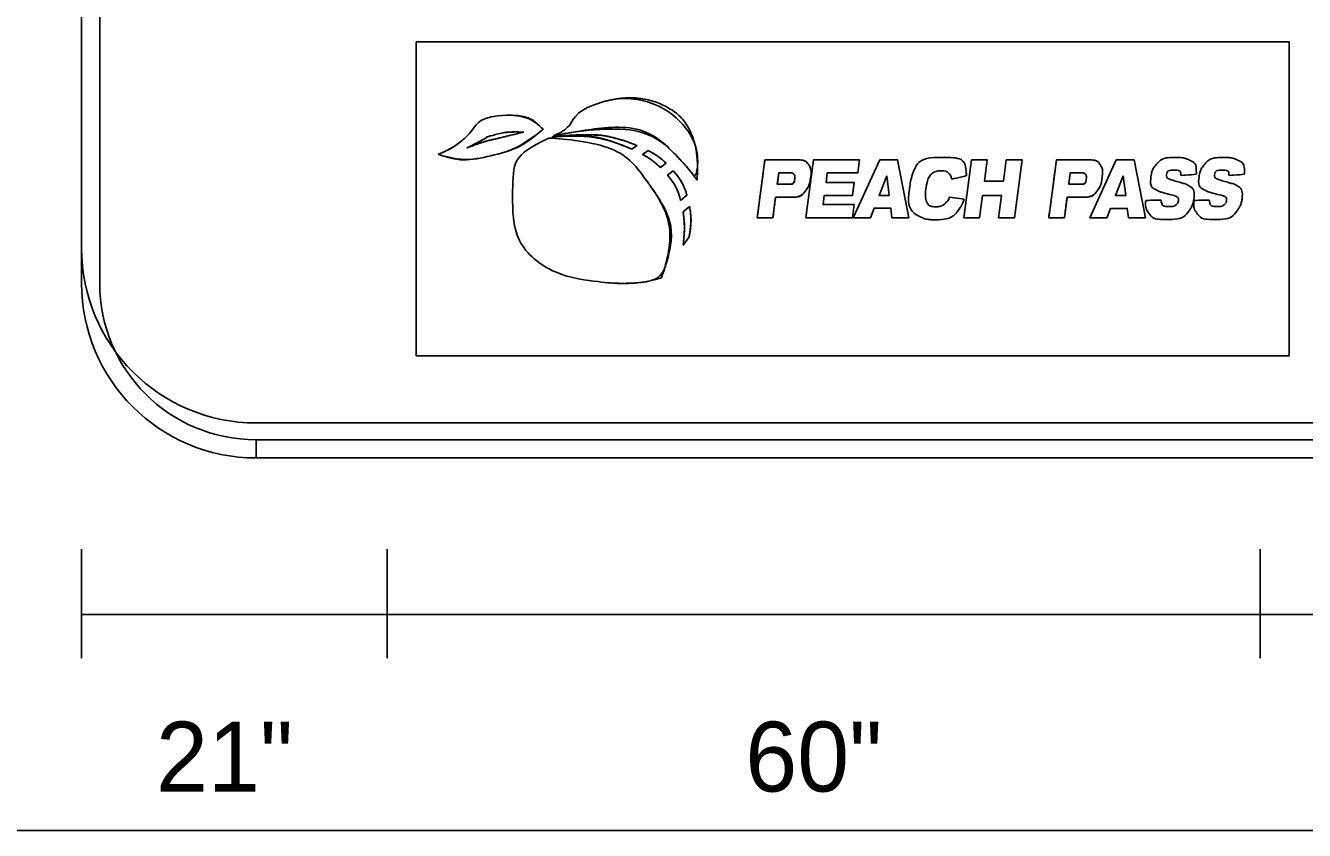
# Model space of a CAD drawing. Extents: x 10268259 to 10268554, y 2141099 to 2141249.
# Drawn here: x 10268353.87 to 10268367.06, y 2141173.53 to 2141181.82 of the extents above; entities that cross this region are included whole.
import ezdxf

# ---------------------------------------------------------------- set-up
doc = ezdxf.new("R2010")
doc.units = 0
for name, color, linetype in [('60', 7, 'Continuous'), ('Default', 7, 'Continuous'), ('GSColorFill', 7, 'Continuous'), ('GSDims', 7, 'Continuous'), ('GSSign', 7, 'Continuous'), ('Level 54', 7, 'Continuous')]:
    doc.layers.add(name, color=color, linetype=linetype)

# ---------------------------------------------------------------- blocks, each defined once
blk = doc.blocks.new('block 26')
at = {"layer": 'Default'}
for p, q in [((103520, 119763), (103447, 119726)), ((108216, 119013), (108535, 119227)), ((109207, 118923), (108863, 118693)), ((109932, 117915), (110273, 118175)), ((110708, 117718), (110360, 117454)), ((111148, 115944), (111527, 116249)), ((111687, 115575), (111294, 115257)), ((111296, 113252), (111655, 113756))]:
    blk.add_line(p, q, dxfattribs=at)
for points, degree in [([(106554, 121853), (104973, 121420), (104564, 120304), (103853, 119966), (103745, 119914), (103639, 119863), (103537, 119814)], 3), ([(106554, 121853), (104973, 121420), (104564, 120304), (103853, 119966), (103745, 119914), (103639, 119863), (103537, 119814), (105021, 120104), (108993, 120617), (111120, 118371), (111504, 117964), (111838, 117553), (112132, 117146), (112357, 120244), (108846, 122480), (106554, 121853)], 3), ([(112132, 117146), (112357, 120244), (108846, 122480), (106554, 121853)], 2), ([(100714, 121038), (99208, 121013), (98659, 120041), (98143, 119598), (97541, 119082), (96638, 118695), (96638, 118695), (96638, 118695), (98100, 118222), (99777, 118609), (101454, 118996), (102917, 120200), (102917, 120200), (102917, 120200), (101968, 121058), (100714, 121038)], 3), ([(100714, 121038), (99208, 121013), (98659, 120041), (98143, 119598), (97541, 119082), (96638, 118695), (96638, 118695)], 3), ([(102917, 120200), (102917, 120200), (101968, 121058), (100714, 121038)], 2), ([(103537, 119814), (105021, 120104), (108993, 120617), (111120, 118371), (111504, 117964), (111838, 117553), (112132, 117146)], 3), ([(96638, 118695), (96638, 118695), (98100, 118222), (99777, 118609), (101454, 118996), (102917, 120200), (102917, 120200)], 3), ([(99777, 119555), (99390, 119469), (98358, 119082), (98358, 119082)], 2), ([(99777, 119555), (99390, 119469), (98358, 119082), (98358, 119082), (99606, 119706), (99431, 119710), (100046, 119872), (100773, 120063), (101755, 120028), (101755, 120028), (100001, 119601), (100076, 119621), (99777, 119555)], 3), ([(98358, 119082), (99606, 119706), (99431, 119710), (100046, 119872), (100773, 120063), (101755, 120028), (101755, 120028)], 3), ([(101755, 120028), (100001, 119601), (100076, 119621), (99777, 119555)], 2), ([(103255, 119674), (101810, 118946), (101088, 118317), (101088, 116389), (101088, 113371), (103558, 111385), (106557, 111039), (107371, 110945), (109062, 111008), (109998, 111313), (110369, 112324), (110876, 114656), (109036, 117219), (107552, 119286), (104259, 119620), (103255, 119674)], 3), ([(103255, 119674), (101810, 118946), (101088, 118317), (101088, 116389), (101088, 113371), (103558, 111385), (106557, 111039), (107371, 110945), (109062, 111008), (109998, 111313)], 3), ([(109998, 111313), (110369, 112324), (110876, 114656), (109036, 117219), (107552, 119286), (104259, 119620), (103255, 119674)], 3), ([(108216, 119013), (108216, 119013), (108535, 119227), (108535, 119227), (106941, 119844), (105037, 119894), (103520, 119763), (103520, 119763), (103447, 119726), (103447, 119726), (104896, 119852), (106699, 119671), (108216, 119013)], 3), ([(103447, 119726), (104896, 119852), (106699, 119671), (108216, 119013)], 2), ([(108535, 119227), (106941, 119844), (105037, 119894), (103520, 119763)], 2), ([(110273, 118175), (109953, 118471), (109593, 118718), (109207, 118923), (109207, 118923), (108863, 118693), (108863, 118693), (109252, 118473), (109614, 118215), (109932, 117915), (109932, 117915), (110273, 118175), (110273, 118175)], 3), ([(108863, 118693), (109252, 118473), (109614, 118215), (109932, 117915)], 2), ([(110273, 118175), (109953, 118471), (109593, 118718), (109207, 118923)], 2), ([(110708, 117718), (110708, 117718), (110360, 117454), (110360, 117454), (110717, 117016), (110983, 116522), (111148, 115944), (111148, 115944), (111527, 116249), (111527, 116249), (111359, 116773), (111089, 117264), (110708, 117718)], 3), ([(110360, 117454), (110717, 117016), (110983, 116522), (111148, 115944)], 2), ([(111527, 116249), (111359, 116773), (111089, 117264), (110708, 117718)], 2), ([(111294, 115257), (111377, 114673), (111380, 114012), (111296, 113252), (111296, 113252), (111655, 113756), (111655, 113756), (111762, 114396), (111776, 115003), (111687, 115575), (111687, 115575), (111294, 115257), (111294, 115257)], 3), ([(111294, 115257), (111377, 114673), (111380, 114012), (111296, 113252)], 2), ([(111655, 113756), (111762, 114396), (111776, 115003), (111687, 115575)], 2)]:
    blk.add_open_spline(points, degree=degree, dxfattribs=at)

msp = doc.modelspace()

# ---------------------------------------------------------------- linework, layer by layer
at = {"layer": '60'}
msp.add_line((10268341.73, 2141173.528), (10268393.98, 2141173.528), dxfattribs=at)
at = {"layer": 'Default'}
for p, q in [((10268361.915, 2141179.843), (10268361.994, 2141180.439)), ((10268361.994, 2141180.439), (10268362.469, 2141180.439)), ((10268362.406, 2141179.843), (10268362.679, 2141180.439)), ((10268362.469, 2141180.439), (10268362.451, 2141180.304)), ((10268362.679, 2141180.439), (10268362.863, 2141180.439)), ((10268362.863, 2141180.439), (10268362.98, 2141179.843)), ((10268363.545, 2141179.843), (10268363.624, 2141180.439)), ((10268363.624, 2141180.439), (10268363.786, 2141180.439)), ((10268363.786, 2141180.439), (10268363.758, 2141180.221)), ((10268363.954, 2141180.221), (10268363.983, 2141180.439)), ((10268363.983, 2141180.439), (10268364.147, 2141180.439)), ((10268364.147, 2141180.439), (10268364.068, 2141179.843)), ((10268364.844, 2141179.842), (10268365.117, 2141180.438)), ((10268365.117, 2141180.438), (10268365.301, 2141180.438)), ((10268365.301, 2141180.438), (10268365.417, 2141179.842)), ((10268362.138, 2141180.304), (10268362.125, 2141180.207)), ((10268362.451, 2141180.304), (10268362.138, 2141180.304)), ((10268362.75, 2141180.273), (10268362.671, 2141180.071)), ((10268362.776, 2141180.071), (10268362.75, 2141180.273)), ((10268365.188, 2141180.273), (10268365.109, 2141180.071)), ((10268365.214, 2141180.071), (10268365.188, 2141180.273)), ((10268362.125, 2141180.207), (10268362.415, 2141180.207)), ((10268362.415, 2141180.207), (10268362.397, 2141180.072)), ((10268363.758, 2141180.221), (10268363.954, 2141180.221)), ((10268362.106, 2141180.072), (10268362.094, 2141179.978)), ((10268362.397, 2141180.072), (10268362.106, 2141180.072)), ((10268362.671, 2141180.071), (10268362.776, 2141180.071)), ((10268363.738, 2141180.071), (10268363.708, 2141179.843)), ((10268363.935, 2141180.071), (10268363.738, 2141180.071)), ((10268363.904, 2141179.843), (10268363.935, 2141180.071)), ((10268365.109, 2141180.071), (10268365.214, 2141180.071)), ((10268362.094, 2141179.978), (10268362.414, 2141179.978)), ((10268362.414, 2141179.978), (10268362.397, 2141179.843)), ((10268362.62, 2141179.94), (10268362.583, 2141179.843)), ((10268362.793, 2141179.94), (10268362.62, 2141179.94)), ((10268362.804, 2141179.843), (10268362.793, 2141179.94)), ((10268365.058, 2141179.939), (10268365.021, 2141179.842)), ((10268365.23, 2141179.939), (10268365.058, 2141179.939)), ((10268365.242, 2141179.842), (10268365.23, 2141179.939)), ((10268362.397, 2141179.843), (10268361.915, 2141179.843)), ((10268362.583, 2141179.843), (10268362.406, 2141179.843)), ((10268362.98, 2141179.843), (10268362.804, 2141179.843)), ((10268363.708, 2141179.843), (10268363.545, 2141179.843)), ((10268364.068, 2141179.843), (10268363.904, 2141179.843)), ((10268365.021, 2141179.842), (10268364.844, 2141179.842)), ((10268365.417, 2141179.842), (10268365.242, 2141179.842))]:
    msp.add_line(p, q, dxfattribs=at)
for points in [[(10268361.726, 2141180.053), (10268361.604, 2141180.053), (10268361.577, 2141179.843), (10268361.416, 2141179.843), (10268361.494, 2141180.439), (10268361.803, 2141180.439)], [(10268362.469, 2141180.439), (10268362.451, 2141180.304), (10268362.138, 2141180.304), (10268362.125, 2141180.207), (10268362.415, 2141180.207), (10268362.397, 2141180.072), (10268362.106, 2141180.072), (10268362.094, 2141179.978), (10268362.414, 2141179.978), (10268362.397, 2141179.843), (10268361.915, 2141179.843), (10268361.994, 2141180.439), (10268362.469, 2141180.439)], [(10268362.679, 2141180.439), (10268362.863, 2141180.439), (10268362.98, 2141179.843), (10268362.804, 2141179.843), (10268362.793, 2141179.94), (10268362.62, 2141179.94), (10268362.583, 2141179.843), (10268362.406, 2141179.843), (10268362.679, 2141180.439)], [(10268363.624, 2141180.439), (10268363.786, 2141180.439), (10268363.758, 2141180.221), (10268363.954, 2141180.221), (10268363.983, 2141180.439), (10268364.147, 2141180.439), (10268364.068, 2141179.843), (10268363.904, 2141179.843), (10268363.935, 2141180.071), (10268363.738, 2141180.071), (10268363.708, 2141179.843), (10268363.545, 2141179.843), (10268363.624, 2141180.439)], [(10268364.732, 2141180.053), (10268364.61, 2141180.053), (10268364.582, 2141179.842), (10268364.421, 2141179.842), (10268364.5, 2141180.439), (10268364.808, 2141180.439)], [(10268365.117, 2141180.438), (10268365.301, 2141180.438), (10268365.417, 2141179.842), (10268365.242, 2141179.842), (10268365.23, 2141179.939), (10268365.058, 2141179.939), (10268365.021, 2141179.842), (10268364.844, 2141179.842), (10268365.117, 2141180.438)], [(10268361.755, 2141180.304), (10268361.637, 2141180.304), (10268361.622, 2141180.187), (10268361.727, 2141180.187)], [(10268362.75, 2141180.273), (10268362.671, 2141180.071), (10268362.776, 2141180.071), (10268362.75, 2141180.273)], [(10268364.761, 2141180.304), (10268364.643, 2141180.304), (10268364.628, 2141180.187), (10268364.732, 2141180.187)], [(10268365.188, 2141180.273), (10268365.109, 2141180.071), (10268365.214, 2141180.071), (10268365.188, 2141180.273)]]:
    msp.add_lwpolyline(points, dxfattribs=at)
for points in [[(10268361.494, 2141180.439), (10268361.494, 2141180.439), (10268361.803, 2141180.439), (10268361.803, 2141180.439), (10268361.86, 2141180.438), (10268361.912, 2141180.436), (10268361.942, 2141180.394), (10268361.956, 2141180.373), (10268361.976, 2141180.33), (10268361.965, 2141180.248), (10268361.959, 2141180.208), (10268361.946, 2141180.162), (10268361.918, 2141180.125), (10268361.868, 2141180.058), (10268361.8, 2141180.053), (10268361.726, 2141180.053), (10268361.726, 2141180.053), (10268361.604, 2141180.053), (10268361.604, 2141180.053), (10268361.604, 2141180.053), (10268361.577, 2141179.843), (10268361.577, 2141179.843), (10268361.577, 2141179.843), (10268361.416, 2141179.843), (10268361.416, 2141179.843), (10268361.416, 2141179.843), (10268361.494, 2141180.439), (10268361.494, 2141180.439)], [(10268361.803, 2141180.439), (10268361.86, 2141180.438), (10268361.912, 2141180.436), (10268361.942, 2141180.394), (10268361.956, 2141180.373), (10268361.976, 2141180.33), (10268361.965, 2141180.248), (10268361.959, 2141180.208), (10268361.946, 2141180.162), (10268361.918, 2141180.125), (10268361.868, 2141180.058), (10268361.8, 2141180.053), (10268361.726, 2141180.053)], [(10268363.154, 2141180.14), (10268363.142, 2141180.05), (10268363.17, 2141179.956), (10268363.262, 2141179.956), (10268363.297, 2141179.956), (10268363.332, 2141179.971), (10268363.359, 2141179.996), (10268363.383, 2141180.019), (10268363.392, 2141180.038), (10268363.399, 2141180.056), (10268363.399, 2141180.056), (10268363.55, 2141180.035), (10268363.55, 2141180.035), (10268363.542, 2141180.013), (10268363.534, 2141179.991), (10268363.515, 2141179.961), (10268363.448, 2141179.853), (10268363.34, 2141179.822), (10268363.241, 2141179.822), (10268363.197, 2141179.822), (10268363.155, 2141179.827), (10268363.115, 2141179.844), (10268363.028, 2141179.882), (10268362.963, 2141179.976), (10268362.985, 2141180.14), (10268363, 2141180.255), (10268363.074, 2141180.464), (10268363.331, 2141180.464), (10268363.55, 2141180.464), (10268363.567, 2141180.332), (10268363.574, 2141180.275), (10268363.574, 2141180.275), (10268363.42, 2141180.24), (10268363.42, 2141180.24), (10268363.416, 2141180.257), (10268363.411, 2141180.28), (10268363.39, 2141180.3), (10268363.368, 2141180.32), (10268363.339, 2141180.327), (10268363.316, 2141180.327), (10268363.244, 2141180.327), (10268363.17, 2141180.267), (10268363.154, 2141180.14)], [(10268363.154, 2141180.14), (10268363.142, 2141180.05), (10268363.17, 2141179.956), (10268363.262, 2141179.956), (10268363.297, 2141179.956), (10268363.332, 2141179.971), (10268363.359, 2141179.996), (10268363.383, 2141180.019), (10268363.392, 2141180.038), (10268363.399, 2141180.056), (10268363.399, 2141180.056), (10268363.55, 2141180.035), (10268363.55, 2141180.035), (10268363.542, 2141180.013), (10268363.534, 2141179.991), (10268363.515, 2141179.961), (10268363.448, 2141179.853), (10268363.34, 2141179.822), (10268363.241, 2141179.822), (10268363.197, 2141179.822), (10268363.155, 2141179.827), (10268363.115, 2141179.844), (10268363.028, 2141179.882), (10268362.963, 2141179.976), (10268362.985, 2141180.14), (10268363, 2141180.255), (10268363.074, 2141180.464), (10268363.331, 2141180.464), (10268363.55, 2141180.464), (10268363.567, 2141180.332), (10268363.574, 2141180.275), (10268363.574, 2141180.275), (10268363.42, 2141180.24), (10268363.42, 2141180.24), (10268363.416, 2141180.257), (10268363.411, 2141180.28), (10268363.39, 2141180.3), (10268363.368, 2141180.32), (10268363.339, 2141180.327), (10268363.316, 2141180.327), (10268363.244, 2141180.327), (10268363.17, 2141180.267), (10268363.154, 2141180.14)], [(10268364.5, 2141180.439), (10268364.5, 2141180.439), (10268364.808, 2141180.439), (10268364.808, 2141180.439), (10268364.866, 2141180.438), (10268364.918, 2141180.436), (10268364.948, 2141180.394), (10268364.962, 2141180.373), (10268364.981, 2141180.33), (10268364.97, 2141180.248), (10268364.965, 2141180.208), (10268364.952, 2141180.162), (10268364.924, 2141180.125), (10268364.874, 2141180.058), (10268364.805, 2141180.053), (10268364.732, 2141180.053), (10268364.732, 2141180.053), (10268364.61, 2141180.053), (10268364.61, 2141180.053), (10268364.61, 2141180.053), (10268364.582, 2141179.842), (10268364.582, 2141179.842), (10268364.582, 2141179.842), (10268364.421, 2141179.842), (10268364.421, 2141179.842), (10268364.421, 2141179.842), (10268364.5, 2141180.439), (10268364.5, 2141180.439)], [(10268364.808, 2141180.439), (10268364.866, 2141180.438), (10268364.918, 2141180.436), (10268364.948, 2141180.394), (10268364.962, 2141180.373), (10268364.981, 2141180.33), (10268364.97, 2141180.248), (10268364.965, 2141180.208), (10268364.952, 2141180.162), (10268364.924, 2141180.125), (10268364.874, 2141180.058), (10268364.805, 2141180.053), (10268364.732, 2141180.053)], [(10268365.634, 2141180.285), (10268365.633, 2141180.276), (10268365.633, 2141180.269), (10268365.636, 2141180.264), (10268365.644, 2141180.245), (10268365.688, 2141180.232), (10268365.712, 2141180.225), (10268365.741, 2141180.215), (10268365.772, 2141180.208), (10268365.801, 2141180.199), (10268365.82, 2141180.194), (10268365.839, 2141180.188), (10268365.856, 2141180.178), (10268365.912, 2141180.148), (10268365.924, 2141180.089), (10268365.917, 2141180.035), (10268365.911, 2141179.995), (10268365.897, 2141179.959), (10268365.88, 2141179.933), (10268365.832, 2141179.858), (10268365.752, 2141179.825), (10268365.63, 2141179.825), (10268365.585, 2141179.825), (10268365.496, 2141179.83), (10268365.451, 2141179.892), (10268365.418, 2141179.938), (10268365.419, 2141179.993), (10268365.421, 2141180.02), (10268365.421, 2141180.02), (10268365.58, 2141180.026), (10268365.58, 2141180.026), (10268365.581, 2141179.987), (10268365.607, 2141179.957), (10268365.671, 2141179.957), (10268365.687, 2141179.957), (10268365.711, 2141179.96), (10268365.729, 2141179.972), (10268365.741, 2141179.98), (10268365.755, 2141179.997), (10268365.757, 2141180.017), (10268365.761, 2141180.045), (10268365.745, 2141180.057), (10268365.733, 2141180.063), (10268365.715, 2141180.071), (10268365.616, 2141180.095), (10268365.595, 2141180.102), (10268365.578, 2141180.107), (10268365.562, 2141180.112), (10268365.546, 2141180.12), (10268365.529, 2141180.129), (10268365.462, 2141180.162), (10268365.476, 2141180.271), (10268365.482, 2141180.316), (10268365.501, 2141180.357), (10268365.528, 2141180.388), (10268365.587, 2141180.457), (10268365.679, 2141180.464), (10268365.729, 2141180.464), (10268365.784, 2141180.464), (10268365.837, 2141180.454), (10268365.863, 2141180.441), (10268365.943, 2141180.406), (10268365.942, 2141180.322), (10268365.943, 2141180.29), (10268365.943, 2141180.29), (10268365.783, 2141180.278), (10268365.783, 2141180.278), (10268365.782, 2141180.297), (10268365.779, 2141180.333), (10268365.711, 2141180.333), (10268365.69, 2141180.333), (10268365.639, 2141180.329), (10268365.634, 2141180.285)], [(10268365.634, 2141180.285), (10268365.633, 2141180.276), (10268365.633, 2141180.269), (10268365.636, 2141180.264), (10268365.644, 2141180.245), (10268365.688, 2141180.232), (10268365.712, 2141180.225), (10268365.741, 2141180.215), (10268365.772, 2141180.208), (10268365.801, 2141180.199), (10268365.82, 2141180.194), (10268365.839, 2141180.188), (10268365.856, 2141180.178), (10268365.912, 2141180.148), (10268365.924, 2141180.089), (10268365.917, 2141180.035), (10268365.911, 2141179.995), (10268365.897, 2141179.959), (10268365.88, 2141179.933), (10268365.832, 2141179.858), (10268365.752, 2141179.825), (10268365.63, 2141179.825), (10268365.585, 2141179.825), (10268365.496, 2141179.83), (10268365.451, 2141179.892), (10268365.418, 2141179.938), (10268365.419, 2141179.993), (10268365.421, 2141180.02), (10268365.421, 2141180.02), (10268365.58, 2141180.026), (10268365.58, 2141180.026), (10268365.581, 2141179.987), (10268365.607, 2141179.957), (10268365.671, 2141179.957), (10268365.687, 2141179.957), (10268365.711, 2141179.96), (10268365.729, 2141179.972), (10268365.741, 2141179.98), (10268365.755, 2141179.997), (10268365.757, 2141180.017), (10268365.761, 2141180.045), (10268365.745, 2141180.057), (10268365.733, 2141180.063), (10268365.715, 2141180.071), (10268365.616, 2141180.095), (10268365.595, 2141180.102), (10268365.578, 2141180.107), (10268365.562, 2141180.112), (10268365.546, 2141180.12), (10268365.529, 2141180.129), (10268365.462, 2141180.162), (10268365.476, 2141180.271), (10268365.482, 2141180.316), (10268365.501, 2141180.357), (10268365.528, 2141180.388), (10268365.587, 2141180.457), (10268365.679, 2141180.464), (10268365.729, 2141180.464), (10268365.784, 2141180.464), (10268365.837, 2141180.454), (10268365.863, 2141180.441), (10268365.943, 2141180.406), (10268365.942, 2141180.322), (10268365.943, 2141180.29), (10268365.943, 2141180.29), (10268365.783, 2141180.278), (10268365.783, 2141180.278), (10268365.782, 2141180.297), (10268365.779, 2141180.333), (10268365.711, 2141180.333), (10268365.69, 2141180.333), (10268365.639, 2141180.329), (10268365.634, 2141180.285)], [(10268366.13, 2141180.285), (10268366.129, 2141180.276), (10268366.13, 2141180.269), (10268366.132, 2141180.264), (10268366.141, 2141180.245), (10268366.184, 2141180.232), (10268366.208, 2141180.225), (10268366.238, 2141180.215), (10268366.268, 2141180.208), (10268366.297, 2141180.199), (10268366.316, 2141180.194), (10268366.335, 2141180.188), (10268366.353, 2141180.178), (10268366.409, 2141180.148), (10268366.42, 2141180.089), (10268366.413, 2141180.035), (10268366.408, 2141179.995), (10268366.393, 2141179.959), (10268366.376, 2141179.933), (10268366.328, 2141179.858), (10268366.248, 2141179.825), (10268366.127, 2141179.825), (10268366.081, 2141179.825), (10268365.992, 2141179.83), (10268365.947, 2141179.892), (10268365.914, 2141179.938), (10268365.916, 2141179.993), (10268365.917, 2141180.02), (10268365.917, 2141180.02), (10268366.077, 2141180.026), (10268366.077, 2141180.026), (10268366.077, 2141179.987), (10268366.103, 2141179.957), (10268366.167, 2141179.957), (10268366.184, 2141179.957), (10268366.208, 2141179.96), (10268366.225, 2141179.972), (10268366.237, 2141179.98), (10268366.251, 2141179.997), (10268366.253, 2141180.017), (10268366.257, 2141180.045), (10268366.242, 2141180.057), (10268366.23, 2141180.063), (10268366.211, 2141180.071), (10268366.112, 2141180.095), (10268366.091, 2141180.102), (10268366.074, 2141180.107), (10268366.058, 2141180.112), (10268366.042, 2141180.12), (10268366.026, 2141180.129), (10268365.958, 2141180.162), (10268365.972, 2141180.271), (10268365.978, 2141180.316), (10268365.998, 2141180.357), (10268366.024, 2141180.388), (10268366.084, 2141180.457), (10268366.175, 2141180.464), (10268366.225, 2141180.464), (10268366.28, 2141180.464), (10268366.333, 2141180.454), (10268366.359, 2141180.441), (10268366.439, 2141180.406), (10268366.439, 2141180.322), (10268366.439, 2141180.29), (10268366.439, 2141180.29), (10268366.279, 2141180.278), (10268366.279, 2141180.278), (10268366.278, 2141180.297), (10268366.275, 2141180.333), (10268366.207, 2141180.333), (10268366.186, 2141180.333), (10268366.136, 2141180.329), (10268366.13, 2141180.285)], [(10268366.13, 2141180.285), (10268366.129, 2141180.276), (10268366.13, 2141180.269), (10268366.132, 2141180.264), (10268366.141, 2141180.245), (10268366.184, 2141180.232), (10268366.208, 2141180.225), (10268366.238, 2141180.215), (10268366.268, 2141180.208), (10268366.297, 2141180.199), (10268366.316, 2141180.194), (10268366.335, 2141180.188), (10268366.353, 2141180.178), (10268366.409, 2141180.148), (10268366.42, 2141180.089), (10268366.413, 2141180.035), (10268366.408, 2141179.995), (10268366.393, 2141179.959), (10268366.376, 2141179.933), (10268366.328, 2141179.858), (10268366.248, 2141179.825), (10268366.127, 2141179.825), (10268366.081, 2141179.825), (10268365.992, 2141179.83), (10268365.947, 2141179.892), (10268365.914, 2141179.938), (10268365.916, 2141179.993), (10268365.917, 2141180.02), (10268365.917, 2141180.02), (10268366.077, 2141180.026), (10268366.077, 2141180.026), (10268366.077, 2141179.987), (10268366.103, 2141179.957), (10268366.167, 2141179.957), (10268366.184, 2141179.957), (10268366.208, 2141179.96), (10268366.225, 2141179.972), (10268366.237, 2141179.98), (10268366.251, 2141179.997), (10268366.253, 2141180.017), (10268366.257, 2141180.045), (10268366.242, 2141180.057), (10268366.23, 2141180.063), (10268366.211, 2141180.071), (10268366.112, 2141180.095), (10268366.091, 2141180.102), (10268366.074, 2141180.107), (10268366.058, 2141180.112), (10268366.042, 2141180.12), (10268366.026, 2141180.129), (10268365.958, 2141180.162), (10268365.972, 2141180.271), (10268365.978, 2141180.316), (10268365.998, 2141180.357), (10268366.024, 2141180.388), (10268366.084, 2141180.457), (10268366.175, 2141180.464), (10268366.225, 2141180.464), (10268366.28, 2141180.464), (10268366.333, 2141180.454), (10268366.359, 2141180.441), (10268366.439, 2141180.406), (10268366.439, 2141180.322), (10268366.439, 2141180.29), (10268366.439, 2141180.29), (10268366.279, 2141180.278), (10268366.279, 2141180.278), (10268366.278, 2141180.297), (10268366.275, 2141180.333), (10268366.207, 2141180.333), (10268366.186, 2141180.333), (10268366.136, 2141180.329), (10268366.13, 2141180.285)], [(10268361.622, 2141180.187), (10268361.622, 2141180.187), (10268361.727, 2141180.187), (10268361.727, 2141180.187), (10268361.754, 2141180.187), (10268361.795, 2141180.188), (10268361.803, 2141180.245), (10268361.805, 2141180.265), (10268361.801, 2141180.283), (10268361.792, 2141180.292), (10268361.782, 2141180.303), (10268361.768, 2141180.304), (10268361.755, 2141180.304), (10268361.755, 2141180.304), (10268361.637, 2141180.304), (10268361.637, 2141180.304), (10268361.637, 2141180.304), (10268361.622, 2141180.187), (10268361.622, 2141180.187)], [(10268361.727, 2141180.187), (10268361.754, 2141180.187), (10268361.795, 2141180.188), (10268361.803, 2141180.245), (10268361.805, 2141180.265), (10268361.801, 2141180.283), (10268361.792, 2141180.292), (10268361.782, 2141180.303), (10268361.768, 2141180.304), (10268361.755, 2141180.304)], [(10268364.628, 2141180.187), (10268364.628, 2141180.187), (10268364.732, 2141180.187), (10268364.732, 2141180.187), (10268364.76, 2141180.187), (10268364.801, 2141180.188), (10268364.808, 2141180.245), (10268364.811, 2141180.265), (10268364.806, 2141180.283), (10268364.798, 2141180.292), (10268364.788, 2141180.303), (10268364.773, 2141180.304), (10268364.761, 2141180.304), (10268364.761, 2141180.304), (10268364.643, 2141180.304), (10268364.643, 2141180.304), (10268364.643, 2141180.304), (10268364.628, 2141180.187), (10268364.628, 2141180.187)], [(10268364.732, 2141180.187), (10268364.76, 2141180.187), (10268364.801, 2141180.188), (10268364.808, 2141180.245), (10268364.811, 2141180.265), (10268364.806, 2141180.283), (10268364.798, 2141180.292), (10268364.788, 2141180.303), (10268364.773, 2141180.304), (10268364.761, 2141180.304)]]:
    msp.add_open_spline(points, degree=3, dxfattribs=at)
at = {"layer": 'GSColorFill'}
for p, q in [((10268354.449, 2141197.528), (10268354.449, 2141179.528)), ((10268356.249, 2141177.728), (10268379.649, 2141177.728))]:
    msp.add_line(p, q, dxfattribs=at)
msp.add_arc((10268356.249, 2141179.528), 1.8, 180, 270, dxfattribs=at)
at = {"layer": 'GSDims'}
for p, q in [((10268354.449, 2141176.428), (10268354.449, 2141175.303)), ((10268357.599, 2141176.428), (10268357.599, 2141175.303)), ((10268366.599, 2141176.428), (10268366.599, 2141175.303)), ((10268354.449, 2141175.753), (10268357.599, 2141175.753)), ((10268357.599, 2141175.753), (10268366.599, 2141175.753)), ((10268366.599, 2141175.753), (10268369.299, 2141175.753))]:
    msp.add_line(p, q, dxfattribs=at)
at = {"layer": 'GSSign'}
msp.add_lwpolyline([(10268357.899, 2141181.655), (10268366.899, 2141181.655), (10268366.899, 2141178.418), (10268357.899, 2141178.418)], close=True, dxfattribs=at)
at = {"layer": 'Level 54'}
for p, q in [((10268354.449, 2141197.168), (10268354.449, 2141179.167)), ((10268354.636, 2141179.167), (10268354.636, 2141197.168)), ((10268356.249, 2141177.367), (10268356.249, 2141177.555)), ((10268379.649, 2141177.555), (10268356.251, 2141177.555)), ((10268356.251, 2141177.555), (10268356.251, 2141177.367)), ((10268356.251, 2141177.367), (10268379.649, 2141177.367))]:
    msp.add_line(p, q, dxfattribs=at)
for radius in [1.8, 1.613]:
    msp.add_arc((10268356.249, 2141179.167), radius, 180, 270, dxfattribs=at)

# ---------------------------------------------------------------- block references
at = {"layer": 'Default', "xscale": 0.00017221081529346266, "yscale": 0.00017221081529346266}
msp.add_blockref('block 26', (10268341.485, 2141160.055), dxfattribs=at)

# ---------------------------------------------------------------- texts
at = {"layer": 'GSDims'}
for s, p in [('21"', (10268355.217, 2141173.929)), ('60"', (10268361.292, 2141173.929))]:
    msp.add_text(s, height=0.72, dxfattribs=at).set_placement(p)

doc.saveas('drawing.dxf')
